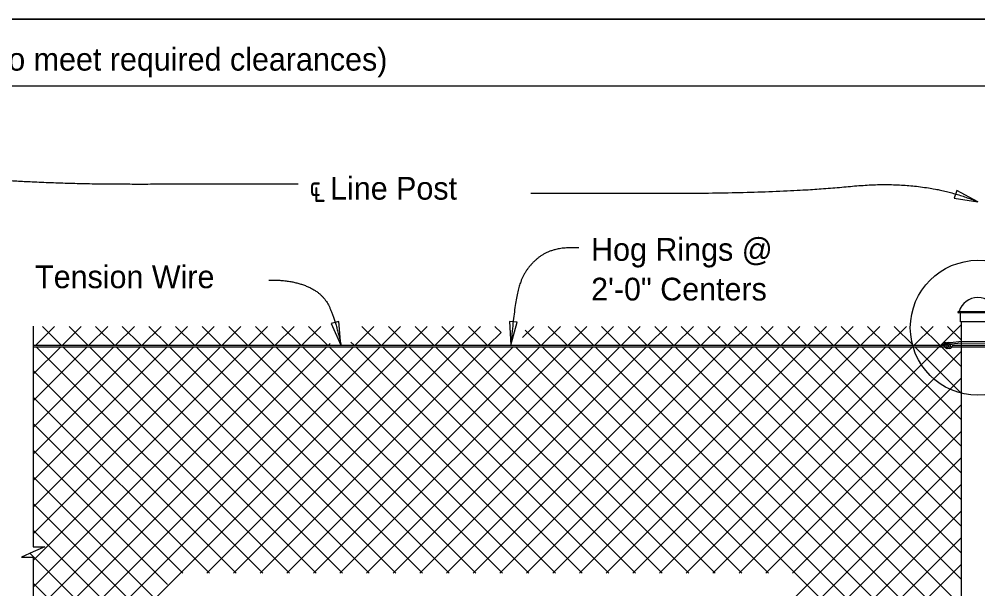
# Model space of a CAD drawing. Extents: x 0 to 41.1, y 0 to 25.9.
# Drawn here: x 16.13 to 24.62, y 20.9 to 25.95 of the extents above; entities that cross this region are included whole.
import ezdxf

# ---------------------------------------------------------------- set-up
doc = ezdxf.new("R2010")
doc.units = 0
for name, color, linetype in [('ActivePts-ConstElements', 7, 'Continuous'), ('Dimension', 7, 'Continuous'), ('Miscellaneous', 7, 'Continuous'), ('Miscellaneous1', 7, 'Continuous'), ('SteelMisc', 7, 'Continuous'), ('SteelMisc_h', 7, 'Continuous'), ('TextStructures', 7, 'Continuous')]:
    doc.layers.add(name, color=color, linetype=linetype)

msp = doc.modelspace()

# ---------------------------------------------------------------- linework, layer by layer
at = {"layer": 'ActivePts-ConstElements'}
msp.add_lwpolyline([(0, 0), (41.0506, 0), (41.0506, 25.9461), (0, 25.9461)], close=True, dxfattribs=at)
msp.add_lwpolyline([(0, 0), (41.0506, 0), (41.0506, 25.9461), (0, 25.9461)], close=True, dxfattribs=at)
msp.add_lwpolyline([(0, 0), (41.0506, 0), (41.0506, 25.9461), (0, 25.9461)], close=True, dxfattribs=at)
at = {"layer": 'Dimension'}
for points in [[(13.615, 25.3556), (15.0787, 25.3556), (15.0787, 25.4589), (15.1237, 25.3556), (15.1687, 25.2523), (15.1687, 25.3556), (28.4596, 25.3556)], [(16.252, 23.2265), (16.252, 21.2702), (16.3553, 21.2702), (16.252, 21.2252), (16.1487, 21.1802), (16.252, 21.1802), (16.252, 20.2867)]]:
    msp.add_lwpolyline(points, dxfattribs=at)
for points in [[(24.6151, 24.3284), (24.4287, 24.4277), (24.4064, 24.3608)], [(18.9764, 23.0579), (18.9562, 23.2681), (18.8881, 23.2497)], [(20.4816, 23.0579), (20.5377, 23.2615), (20.4675, 23.2686)]]:
    msp.add_lwpolyline(points, close=True, dxfattribs=at)
msp.add_circle((24.615, 23.212), 0.5976, dxfattribs=at)
for points in [[(18.5966, 24.4827), (17.7933, 24.4827), (16.4039, 24.4827), (15.2225, 24.5773), (14.615, 24.6814)], [(20.6562, 24.4046), (21.1029, 24.4046), (22.8703, 24.4046), (24.1369, 24.5276), (24.615, 24.3283)], [(21.0813, 23.9198), (20.8634, 23.9322), (20.6196, 23.7577), (20.5135, 23.4738), (20.4817, 23.0578)], [(18.338, 23.6332), (18.5184, 23.6403), (18.8013, 23.5305), (18.9216, 23.311), (18.9764, 23.0578)]]:
    msp.add_open_spline(points, degree=2, dxfattribs=at)
at = {"layer": 'Miscellaneous'}
for p, q in [((16.2736, 23.0578), (16.4402, 23.2245)), ((16.3328, 23.2245), (16.4994, 23.0578)), ((16.5093, 23.0578), (16.6759, 23.2245)), ((16.5685, 23.2245), (16.7352, 23.0578)), ((16.745, 23.0578), (16.9116, 23.2245)), ((16.8042, 23.2245), (16.9709, 23.0578)), ((16.9807, 23.0578), (17.1473, 23.2245)), ((17.0399, 23.2245), (17.2066, 23.0578)), ((17.2164, 23.0578), (17.383, 23.2245)), ((17.2756, 23.2245), (17.4423, 23.0578)), ((17.4521, 23.0578), (17.6187, 23.2245)), ((17.5113, 23.2245), (17.678, 23.0578)), ((17.6878, 23.0578), (17.8544, 23.2245)), ((17.747, 23.2245), (17.9137, 23.0578)), ((17.9235, 23.0578), (18.0901, 23.2245)), ((17.9827, 23.2245), (18.1494, 23.0578)), ((18.1592, 23.0578), (18.3258, 23.2245)), ((18.2184, 23.2245), (18.3851, 23.0578)), ((18.3949, 23.0578), (18.5615, 23.2245)), ((18.4541, 23.2245), (18.6208, 23.0578)), ((18.6306, 23.0578), (18.7972, 23.2245)), ((18.6898, 23.2245), (18.8565, 23.0578)), ((19.102, 23.0578), (19.2687, 23.2245)), ((19.1612, 23.2245), (19.3279, 23.0578)), ((19.3377, 23.0578), (19.5044, 23.2245)), ((19.3969, 23.2245), (19.5636, 23.0578)), ((19.5734, 23.0578), (19.7401, 23.2245)), ((19.6326, 23.2245), (19.7993, 23.0578)), ((19.8091, 23.0578), (19.9758, 23.2245)), ((19.8683, 23.2245), (20.035, 23.0578)), ((20.0448, 23.0578), (20.2115, 23.2245)), ((20.104, 23.2245), (20.2707, 23.0578)), ((20.3397, 23.2245), (20.3934, 23.1708)), ((20.5829, 23.1245), (20.6829, 23.2245)), ((20.6086, 23.1914), (20.7421, 23.0578)), ((20.7519, 23.0578), (20.9186, 23.2245)), ((20.8111, 23.2245), (20.9778, 23.0578)), ((20.9876, 23.0578), (21.1543, 23.2245)), ((21.0468, 23.2245), (21.2135, 23.0578)), ((21.2233, 23.0578), (21.39, 23.2245)), ((21.2825, 23.2245), (21.4492, 23.0578)), ((21.459, 23.0578), (21.6257, 23.2245)), ((21.5182, 23.2245), (21.6849, 23.0578)), ((21.6947, 23.0578), (21.8614, 23.2245)), ((21.7539, 23.2245), (21.9206, 23.0578)), ((21.9304, 23.0578), (22.0971, 23.2245)), ((21.9896, 23.2245), (22.1563, 23.0578)), ((22.1661, 23.0578), (22.3328, 23.2245)), ((22.2253, 23.2245), (22.392, 23.0578)), ((22.2674, 21.0378), (24.4692, 23.2396)), ((22.4018, 23.0578), (22.5685, 23.2245)), ((22.461, 23.2245), (22.6277, 23.0578)), ((22.6375, 23.0578), (22.8042, 23.2245)), ((22.6967, 23.2245), (22.8634, 23.0578)), ((22.8732, 23.0578), (23.0399, 23.2245)), ((22.9324, 23.2245), (23.0991, 23.0578)), ((23.1089, 23.0578), (23.2756, 23.2245)), ((23.1681, 23.2245), (23.3348, 23.0578)), ((23.3446, 23.0578), (23.5113, 23.2245)), ((23.4038, 23.2245), (23.5705, 23.0578)), ((23.5803, 23.0578), (23.747, 23.2245)), ((23.6396, 23.2245), (23.8062, 23.0578)), ((23.816, 23.0578), (23.9827, 23.2245)), ((23.8753, 23.2245), (24.0419, 23.0578)), ((24.0517, 23.0578), (24.2184, 23.2245)), ((24.111, 23.2245), (24.2776, 23.0578)), ((24.2874, 23.0578), (24.4541, 23.2245)), ((24.3467, 23.2245), (24.4692, 23.1019)), ((20.2805, 23.0578), (20.3934, 23.1708)), ((16.252, 19.7364), (19.5586, 23.0431)), ((16.252, 20.2078), (19.0872, 23.0431)), ((16.252, 21.1506), (18.1444, 23.0431)), ((16.252, 20.6792), (18.6158, 23.0431)), ((16.252, 19.9721), (19.3229, 23.0431)), ((16.252, 20.4435), (18.8515, 23.0431)), ((16.252, 20.9149), (18.3801, 23.0431)), ((16.252, 21.3863), (17.9087, 23.0431)), ((16.252, 21.622), (17.673, 23.0431)), ((16.252, 22.0934), (17.2016, 23.0431)), ((16.252, 21.8577), (17.4373, 23.0431)), ((16.252, 22.5648), (16.7302, 23.0431)), ((16.252, 23.0363), (16.2588, 23.0431)), ((16.252, 22.3291), (16.9659, 23.0431)), ((16.252, 22.8005), (16.4945, 23.0431)), ((16.2785, 23.0431), (18.2838, 21.0378)), ((16.5142, 23.0431), (18.5195, 21.0378)), ((16.7499, 23.0431), (18.7552, 21.0378)), ((16.9856, 23.0431), (18.9909, 21.0378)), ((17.2213, 23.0431), (19.2266, 21.0378)), ((17.457, 23.0431), (19.4623, 21.0378)), ((17.6927, 23.0431), (19.698, 21.0378)), ((17.7891, 21.0378), (19.7943, 23.0431)), ((17.9284, 23.0431), (19.9337, 21.0378)), ((18.0248, 21.0378), (20.03, 23.0431)), ((18.1641, 23.0431), (20.1694, 21.0378)), ((18.2605, 21.0378), (20.2657, 23.0431)), ((18.3998, 23.0431), (20.4051, 21.0378)), ((18.4962, 21.0378), (20.5014, 23.0431)), ((18.6355, 23.0431), (20.6408, 21.0378)), ((18.7319, 21.0378), (20.7372, 23.0431)), ((18.8663, 23.0578), (18.8813, 23.0728)), ((18.8712, 23.0431), (20.8765, 21.0378)), ((18.9676, 21.0378), (20.9729, 23.0431)), ((19.065, 23.085), (19.0922, 23.0578)), ((19.1069, 23.0431), (21.1122, 21.0378)), ((19.2033, 21.0378), (21.2086, 23.0431)), ((19.3426, 23.0431), (21.3479, 21.0378)), ((19.439, 21.0378), (21.4443, 23.0431)), ((19.5783, 23.0431), (21.5836, 21.0378)), ((19.6747, 21.0378), (21.68, 23.0431)), ((19.814, 23.0431), (21.8193, 21.0378)), ((19.9104, 21.0378), (21.9157, 23.0431)), ((20.0497, 23.0431), (22.055, 21.0378)), ((20.1461, 21.0378), (22.1514, 23.0431)), ((20.2854, 23.0431), (22.2907, 21.0378)), ((20.3818, 21.0378), (22.3871, 23.0431)), ((20.5211, 23.0431), (22.5264, 21.0378)), ((20.6175, 21.0378), (22.6228, 23.0431)), ((20.7568, 23.0431), (22.7621, 21.0378)), ((20.8532, 21.0378), (22.8585, 23.0431)), ((20.9925, 23.0431), (24.4692, 19.5664)), ((21.0889, 21.0378), (23.0942, 23.0431)), ((21.2282, 23.0431), (24.4692, 19.8021)), ((21.3246, 21.0378), (23.3299, 23.0431)), ((21.4639, 23.0431), (24.4692, 20.0378)), ((21.5603, 21.0378), (23.5656, 23.0431)), ((21.6996, 23.0431), (24.4692, 20.2735)), ((21.796, 21.0378), (23.8013, 23.0431)), ((21.9353, 23.0431), (24.4692, 20.5092)), ((22.0317, 21.0378), (24.037, 23.0431)), ((22.1711, 23.0431), (24.4692, 20.7449)), ((22.4068, 23.0431), (24.4692, 20.9806)), ((22.5031, 21.0378), (24.4692, 23.0039)), ((22.6425, 23.0431), (24.4692, 21.2163)), ((22.8782, 23.0431), (24.4692, 21.452)), ((23.1139, 23.0431), (24.4692, 21.6877)), ((23.3496, 23.0431), (24.4692, 21.9234)), ((23.5853, 23.0431), (24.4692, 22.1591)), ((23.821, 23.0431), (24.4692, 22.3948)), ((24.0567, 23.0431), (24.4692, 22.6305)), ((24.2924, 23.0431), (24.4692, 22.8662)), ((16.252, 22.8339), (18.0481, 21.0378)), ((22.7388, 21.0378), (24.4692, 22.7682)), ((16.252, 22.5982), (17.8124, 21.0378)), ((22.9745, 21.0378), (24.4692, 22.5325)), ((16.252, 22.3625), (17.5767, 21.0378)), ((22.9985, 20.8261), (24.4692, 22.2968)), ((16.252, 22.1268), (17.4417, 20.9371)), ((22.9985, 20.5904), (24.4692, 22.0611)), ((16.252, 21.8911), (17.4417, 20.7014)), ((22.9985, 20.3547), (24.4692, 21.8254)), ((16.252, 21.6554), (17.4417, 20.4657)), ((22.9985, 20.119), (24.4692, 21.5897)), ((16.252, 21.4197), (17.4417, 20.23)), ((21.9677, 18.8525), (24.4692, 21.354)), ((16.2232, 21.2127), (17.4417, 19.9943)), ((22.2034, 18.8525), (24.4692, 21.1183)), ((16.252, 20.9483), (19.7943, 17.4059))]:
    msp.add_line(p, q, dxfattribs=at)
at = {"layer": 'Miscellaneous1'}
msp.add_lwpolyline([(0, 25.9461), (41.0506, 25.9461), (41.0506, 0), (0, 0)], close=True, dxfattribs=at)
at = {"layer": 'SteelMisc'}
for p, q in [((24.4427, 23.3564), (24.7873, 23.3564)), ((24.7873, 23.3442), (24.4427, 23.3442)), ((24.461, 23.2645), (24.461, 23.3442)), ((24.7691, 23.2645), (24.461, 23.2645)), ((24.4692, 16.8894), (24.4692, 23.2644)), ((24.4692, 23.0904), (24.3743, 23.0793)), ((24.4692, 23.0904), (24.7604, 23.0921)), ((16.252, 23.0578), (24.2941, 23.0578)), ((16.252, 23.0431), (24.3207, 23.0431)), ((24.304, 23.0578), (24.3172, 23.0578)), ((24.4692, 23.0759), (24.3766, 23.0664)), ((24.3856, 23.0431), (24.4692, 23.0431)), ((24.387, 23.0578), (24.4692, 23.0578)), ((24.4692, 23.0759), (24.7604, 23.0776))]:
    msp.add_line(p, q, dxfattribs=at)
msp.add_arc((24.4429, 23.3502), 0.00613, 91.1647, 268.8353, dxfattribs=at)
for centre, major_axis, ratio, start_param, end_param in [((24.6157, 23.3154), (0.1711, 0), 0.957868, 0.252602, 2.888574), ((24.3283, 23.0436), (0.0373, 0), 0.957868, 1.486836, 3.108042), ((24.3494, 23.0039), (-0.0724, 0), 0.957868, 5.162149, 5.652106), ((24.3419, 23.0555), (-0.0249, 0), 0.957868, 6.009018, 7.089857), ((24.3408, 23.058), (0.023, 0), 0.957868, 1.29026, 2.970541), ((24.3433, 23.0515), (0.0231, 0), 0.957868, 3.779554, 4.879821), ((24.3595, 23.0527), (0.0295, 0), 0.957868, 1.220941, 4.039556), ((24.373, 23.0544), (-0.0303, -0.0108), 0.724765, 4.35367, 6.324556), ((24.3494, 23.0458), (0.0206, -0.0021), 0.798607, 4.32653, 5.220153), ((24.3629, 23.0458), (0.0206, -0.0021), 0.798607, 3.333154, 5.220153), ((24.3697, 23.0504), (-0.0139, 0), 0.957868, 5.22362, 6.905413), ((24.364, 23.048), (-0.00795, 0), 0.957868, 6.140374, 9.314262), ((24.3781, 23.0415), (-0.0259, 0), 0.957868, 4.777514, 5.62749), ((24.3624, 23.0538), (0.0119, 0), 0.957868, 5.725876, 7.416677), ((24.3555, 23.0646), (0.0391, 0), 0.957868, 5.082588, 5.41974), ((24.3624, 23.0538), (0.0119, 0), 0.957868, 5.639684, 5.723117), ((24.3626, 23.0525), (0.0251, 0), 0.957868, 5.531357, 6.227833), ((24.3626, 23.0525), (0.0251, 0), 0.957868, 0.407687, 0.609214)]:
    msp.add_ellipse(centre, major_axis=major_axis, ratio=ratio, start_param=start_param, end_param=end_param, dxfattribs=at)
at = {"layer": 'SteelMisc_h'}
for p, q in [((24.4692, 23.0578), (24.7609, 23.0578)), ((24.4692, 23.0431), (24.7609, 23.0431))]:
    msp.add_line(p, q, dxfattribs=at)

# ---------------------------------------------------------------- texts
at = {"layer": 'Dimension'}
for s, p in [('Hog Rings @ ', (21.1911, 23.8055)), ('2\'-0" Centers', (21.1911, 23.4535))]:
    msp.add_text(s, height=0.2016, dxfattribs=at).set_placement(p)
at = {"layer": 'TextStructures'}
for s, p in [('Equal Spaces @ 10\'-0" Max. (Posts may be shifted minimally to meet required clearances)', (8.5826, 25.4902)), ('℄ Line Post', (18.6958, 24.347)), ('Tension Wire', (16.268, 23.5627))]:
    msp.add_text(s, height=0.2016, dxfattribs=at).set_placement(p)

doc.saveas('drawing.dxf')
